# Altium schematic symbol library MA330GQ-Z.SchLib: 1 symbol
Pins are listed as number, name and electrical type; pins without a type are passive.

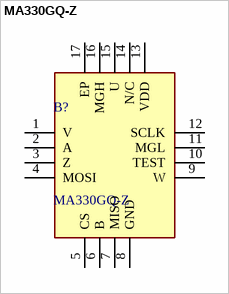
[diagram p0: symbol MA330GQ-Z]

## MA330GQ-Z
designator B?
14-Bit Digital Contactless Angle Sensor with ABZ & UVW Incremental Outputs 16-Pin QFN T/R - Tape and Reel; Manufacturer_Name: Monolithic Power Systems (MPS); Geometry.Height: 1mm
footprint QFN50P300X300X100-17N-D
pins: 1 V, 2 A, 3 Z, 4 MOSI, 5 CS, 6 B, 7 MISO, 8 GND, 9 W, 10 TEST, 11 MGL, 12 SCLK, 13 VDD, 14 N/C, 15 U, 16 MGH, 17 EP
